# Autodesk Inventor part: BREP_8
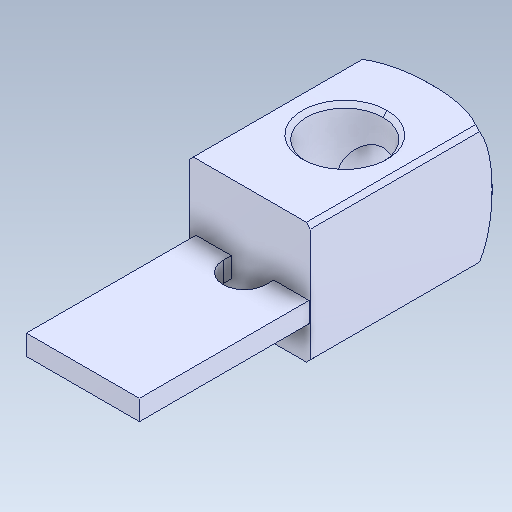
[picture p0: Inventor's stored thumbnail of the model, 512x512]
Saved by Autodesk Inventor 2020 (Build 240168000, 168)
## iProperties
Created: 2017-09
Part Number: BREP_8
Material: Générique
Document SubType Name: Modeling
Designer: bruno
Density: 1 g/cm^3
Appearance: Par défaut
Author: bruno
Sending System: SolidWorks 2016
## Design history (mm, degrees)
feature "Importée1"
node "Solide1"
